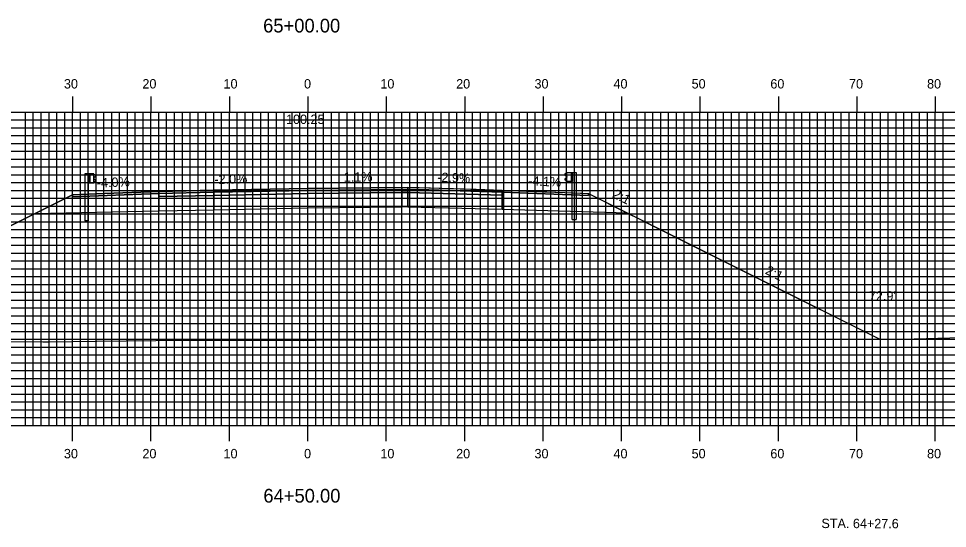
# Model space of a CAD drawing. Extents: x 1758643 to 1758986, y 442591 to 442811.
# Drawn here: x 1758771.8 to 1758890.2, y 442655.5 to 442720.6 of the extents above; entities that cross this region are included whole.
import ezdxf

# ---------------------------------------------------------------- set-up
doc = ezdxf.new("R2010")
doc.units = 0
for name, color, linetype in [('ANNOTATION', 7, 'Continuous'), ('BORING - REFUSAL', 7, 'Continuous'), ('D_Guardrail_Beam_Lt', 7, 'Continuous'), ('D_Guardrail_Beam_Rt', 7, 'Continuous'), ('D_Roadway_Centerline', 7, 'Continuous'), ('D_Roadway_Centerline_Text', 7, 'Continuous'), ('D_Roadway_Edge_Shoulder', 7, 'Continuous'), ('D_Roadway_Edge_TW', 7, 'Continuous'), ('D_Roadway_Pavement', 7, 'Continuous'), ('D_Roadway_SlopeLines', 7, 'Continuous'), ('D_Roadway_SubGrade', 7, 'Continuous'), ('D_Text_Standard', 7, 'Continuous'), ('H_V ANNOTATION', 7, 'Continuous'), ('MAJOR', 7, 'Continuous'), ('MINOR', 7, 'Continuous'), ('S_Roadway_Centerline', 7, 'Continuous')]:
    doc.layers.add(name, color=color, linetype=linetype)

msp = doc.modelspace()

# ---------------------------------------------------------------- linework, layer by layer
at = {"layer": 'D_Guardrail_Beam_Lt'}
for p, q in [((1758780.21, 442700.8), (1758780.21, 442694.8)), ((1758780.68, 442700.8), (1758780.21, 442700.8)), ((1758781.37, 442700.8), (1758780.68, 442700.8)), ((1758780.68, 442700.8), (1758780.68, 442699.63)), ((1758780.74, 442700.8), (1758780.74, 442699.63)), ((1758780.85, 442700.8), (1758780.85, 442699.63)), ((1758781.37, 442699.63), (1758781.37, 442700.8)), ((1758781.37, 442700.72), (1758781.44, 442700.7)), ((1758781.37, 442700.25), (1758781.37, 442700.18)), ((1758781.6, 442700.45), (1758781.41, 442700.31)), ((1758781.41, 442700.12), (1758781.6, 442699.98)), ((1758781.46, 442700.69), (1758781.6, 442700.59)), ((1758780.68, 442699.63), (1758781.37, 442699.63)), ((1758780.7, 442694.8), (1758780.7, 442699.63)), ((1758781.44, 442699.73), (1758781.37, 442699.72)), ((1758781.6, 442699.84), (1758781.46, 442699.74)), ((1758780.7, 442694.8), (1758780.21, 442694.8))]:
    msp.add_line(p, q, dxfattribs=at)
for centre, major_axis, start_param, end_param in [((1758781.45, 442700.25), (-0.0789, 0), 5.323254, 6.283185), ((1758781.45, 442700.18), (-0.0789, 0), 6.283185, 7.243116), ((1758781.43, 442700.66), (0.0417, 0), 0.959931, 1.376053), ((1758781.55, 442700.52), (0.0877, 0), 5.323254, 7.243116), ((1758781.43, 442699.77), (0.0417, 0), 4.907132, 5.323254), ((1758781.55, 442699.91), (0.0877, 0), 5.323254, 7.243116)]:
    msp.add_ellipse(centre, major_axis=major_axis, ratio=0.995501, start_param=start_param, end_param=end_param, dxfattribs=at)
at = {"layer": 'D_Guardrail_Beam_Rt'}
for p, q in [((1758841.6, 442700.87), (1758841.46, 442700.77)), ((1758841.46, 442700.62), (1758841.65, 442700.49)), ((1758841.65, 442700.29), (1758841.46, 442700.15)), ((1758841.69, 442700.89), (1758841.62, 442700.87)), ((1758841.69, 442700.97), (1758842.38, 442700.97)), ((1758841.69, 442699.81), (1758841.69, 442700.97)), ((1758841.69, 442700.42), (1758841.69, 442700.35)), ((1758842.21, 442700.97), (1758842.21, 442699.81)), ((1758842.32, 442700.97), (1758842.32, 442699.81)), ((1758842.38, 442700.97), (1758842.85, 442700.97)), ((1758842.38, 442700.97), (1758842.38, 442699.81)), ((1758842.85, 442700.97), (1758842.85, 442694.97)), ((1758841.46, 442700.01), (1758841.6, 442699.91)), ((1758841.62, 442699.9), (1758841.69, 442699.89)), ((1758842.38, 442699.81), (1758841.69, 442699.81)), ((1758842.36, 442694.97), (1758842.36, 442699.81)), ((1758842.36, 442694.97), (1758842.85, 442694.97))]:
    msp.add_line(p, q, dxfattribs=at)
for centre, major_axis, start_param, end_param in [((1758841.51, 442700.7), (-0.0877, 0), 5.323254, 7.243116), ((1758841.51, 442700.08), (-0.0877, 0), 5.323254, 7.243116), ((1758841.62, 442700.83), (-0.0417, 0), 4.907132, 5.323254), ((1758841.61, 442700.42), (0.0789, 0), 0, 0.959931), ((1758841.61, 442700.35), (0.0789, 0), 5.323254, 6.283185), ((1758841.62, 442699.94), (-0.0417, 0), 0.959931, 1.376053)]:
    msp.add_ellipse(centre, major_axis=major_axis, ratio=0.995501, start_param=start_param, end_param=end_param, dxfattribs=at)
at = {"layer": 'D_Roadway_Centerline'}
msp.add_lwpolyline([(1758740.03, 442678.79), (1758773.89, 442695.72), (1758778.64, 442698.1), (1758781.64, 442698.22), (1758789.64, 442698.54), (1758796.65, 442698.68), (1758808.65, 442698.92), (1758820.65, 442699.05), (1758821.41, 442699.06), (1758830.1, 442698.81), (1758833.42, 442698.71), (1758837.57, 442698.54), (1758841.42, 442698.39), (1758843.56, 442698.3), (1758844.42, 442698.27), (1758845.53, 442697.71), (1758849.39, 442695.78), (1758850.9, 442695.02), (1758852.29, 442694.33), (1758866.5, 442687.22), (1758881.57, 442679.68)], dxfattribs=at)
at = {"layer": 'D_Roadway_Edge_Shoulder'}
for points in [[(1758789.64, 442698.54), (1758781.64, 442698.22), (1758781.64, 442698.22), (1758778.64, 442698.1), (1758778.64, 442697.85), (1758789.64, 442698.29)], [(1758833.42, 442698.71), (1758841.42, 442698.39), (1758841.42, 442698.39), (1758844.42, 442698.27), (1758844.42, 442698.02), (1758833.42, 442698.46)]]:
    msp.add_lwpolyline(points, close=True, dxfattribs=at)
at = {"layer": 'D_Roadway_Edge_TW'}
for points in [[(1758820.65, 442698.8), (1758820.65, 442699.05), (1758808.65, 442698.92), (1758796.65, 442698.68), (1758796.65, 442698.43), (1758808.65, 442698.67)], [(1758820.65, 442699.05), (1758821.41, 442699.06), (1758821.41, 442698.81), (1758820.65, 442698.8)], [(1758821.41, 442699.06), (1758833.42, 442698.71), (1758833.42, 442698.46), (1758821.41, 442698.81)], [(1758796.65, 442698.68), (1758789.64, 442698.54), (1758789.64, 442698.29), (1758796.65, 442698.43)]]:
    msp.add_lwpolyline(points, close=True, dxfattribs=at)
msp.add_lwpolyline([(1758820.65, 442699.05), (1758820.65, 442698.8)], dxfattribs=at)
msp.add_lwpolyline([(1758820.65, 442699.05), (1758820.65, 442698.8)], dxfattribs=at)
at = {"layer": 'D_Roadway_Pavement'}
for points in [[(1758796.65, 442698.43), (1758789.64, 442698.29), (1758789.64, 442697.87), (1758796.65, 442698.01)], [(1758820.65, 442698.38), (1758820.65, 442698.8), (1758808.65, 442698.67), (1758796.65, 442698.43), (1758796.65, 442698.01), (1758808.65, 442698.25)], [(1758820.65, 442698.8), (1758821.41, 442698.81), (1758821.41, 442698.39), (1758820.65, 442698.38)], [(1758821.41, 442698.81), (1758833.42, 442698.46), (1758833.42, 442698.05), (1758821.41, 442698.39)]]:
    msp.add_lwpolyline(points, close=True, dxfattribs=at)
for points in [[(1758789.64, 442698.29), (1758789.64, 442697.87)], [(1758789.64, 442698.29), (1758789.64, 442697.87)], [(1758820.65, 442698.8), (1758820.65, 442698.38)], [(1758820.65, 442698.8), (1758820.65, 442698.38)], [(1758833.42, 442698.46), (1758833.42, 442698.05)], [(1758833.42, 442698.46), (1758833.42, 442698.05)]]:
    msp.add_lwpolyline(points, dxfattribs=at)
at = {"layer": 'D_Roadway_SlopeLines'}
for points in [[(1758778.64, 442698.1), (1758740.03, 442678.79)], [(1758844.42, 442698.27), (1758881.57, 442679.68)]]:
    msp.add_lwpolyline(points, dxfattribs=at)
at = {"layer": 'D_Roadway_SubGrade'}
for points in [[(1758789.64, 442697.87), (1758789.64, 442698.29), (1758778.64, 442697.85), (1758778.64, 442698.1), (1758773.89, 442695.72), (1758789.64, 442696.04)], [(1758796.65, 442698.01), (1758789.64, 442697.87), (1758789.64, 442696.04), (1758796.65, 442696.18)], [(1758820.65, 442696.55), (1758820.65, 442698.38), (1758808.65, 442698.25), (1758796.65, 442698.01), (1758796.65, 442696.18), (1758808.65, 442696.42)], [(1758820.65, 442698.38), (1758821.41, 442698.39), (1758821.41, 442696.53), (1758820.65, 442696.55)], [(1758821.41, 442698.39), (1758833.42, 442698.05), (1758833.42, 442696.21), (1758821.41, 442696.53)], [(1758833.42, 442698.05), (1758833.42, 442698.46), (1758844.42, 442698.02), (1758844.42, 442698.27), (1758849.39, 442695.78), (1758833.42, 442696.21)]]:
    msp.add_lwpolyline(points, close=True, dxfattribs=at)
msp.add_lwpolyline([(1758820.65, 442698.38), (1758820.65, 442696.55)], dxfattribs=at)
msp.add_lwpolyline([(1758820.65, 442698.38), (1758820.65, 442696.55)], dxfattribs=at)
at = {"layer": 'MAJOR'}
for p, q in [((1758778.65, 442710.67), (1758778.65, 442708.67)), ((1758788.65, 442710.67), (1758788.65, 442708.67)), ((1758798.65, 442710.67), (1758798.65, 442708.67)), ((1758808.65, 442710.67), (1758808.65, 442708.67)), ((1758818.65, 442710.67), (1758818.65, 442708.67)), ((1758828.65, 442710.67), (1758828.65, 442708.67)), ((1758838.65, 442710.67), (1758838.65, 442708.67)), ((1758848.65, 442710.67), (1758848.65, 442708.67)), ((1758858.65, 442710.67), (1758858.65, 442708.67)), ((1758868.65, 442710.67), (1758868.65, 442708.67)), ((1758878.65, 442710.67), (1758878.65, 442708.67)), ((1758888.65, 442710.67), (1758888.65, 442708.67)), ((1758668.65, 442708.67), (1758948.65, 442708.67)), ((1758668.65, 442708.67), (1758948.65, 442708.67)), ((1758778.65, 442668.67), (1758778.65, 442708.67)), ((1758788.65, 442668.67), (1758788.65, 442708.67)), ((1758798.65, 442668.67), (1758798.65, 442708.67)), ((1758808.65, 442668.67), (1758808.65, 442708.67)), ((1758818.65, 442668.67), (1758818.65, 442708.67)), ((1758828.65, 442668.67), (1758828.65, 442708.67)), ((1758838.65, 442668.67), (1758838.65, 442708.67)), ((1758848.65, 442668.67), (1758848.65, 442708.67)), ((1758858.65, 442668.67), (1758858.65, 442708.67)), ((1758868.65, 442668.67), (1758868.65, 442708.67)), ((1758878.65, 442668.67), (1758878.65, 442708.67)), ((1758888.65, 442668.67), (1758888.65, 442708.67)), ((1758668.65, 442703.67), (1758948.65, 442703.67)), ((1758668.65, 442698.67), (1758948.65, 442698.67)), ((1758668.65, 442693.67), (1758948.65, 442693.67)), ((1758668.65, 442688.67), (1758948.65, 442688.67)), ((1758668.65, 442683.67), (1758948.65, 442683.67)), ((1758668.65, 442678.67), (1758948.65, 442678.67)), ((1758668.65, 442673.67), (1758948.65, 442673.67)), ((1758668.65, 442668.67), (1758948.65, 442668.67)), ((1758668.65, 442668.67), (1758948.65, 442668.67)), ((1758778.65, 442666.66), (1758778.65, 442668.67)), ((1758788.65, 442666.66), (1758788.65, 442668.67)), ((1758798.65, 442666.66), (1758798.65, 442668.67)), ((1758808.65, 442666.66), (1758808.65, 442668.67)), ((1758818.65, 442666.66), (1758818.65, 442668.67)), ((1758828.65, 442666.66), (1758828.65, 442668.67)), ((1758838.65, 442666.66), (1758838.65, 442668.67)), ((1758848.65, 442666.66), (1758848.65, 442668.67)), ((1758858.65, 442666.66), (1758858.65, 442668.67)), ((1758868.65, 442666.66), (1758868.65, 442668.67)), ((1758878.65, 442666.66), (1758878.65, 442668.67)), ((1758888.65, 442666.66), (1758888.65, 442668.67))]:
    msp.add_line(p, q, dxfattribs=at)
at = {"layer": 'MINOR'}
for p, q in [((1758772.65, 442668.67), (1758772.65, 442708.67)), ((1758773.65, 442668.67), (1758773.65, 442708.67)), ((1758774.65, 442668.67), (1758774.65, 442708.67)), ((1758775.65, 442668.67), (1758775.65, 442708.67)), ((1758776.65, 442668.67), (1758776.65, 442708.67)), ((1758777.65, 442668.67), (1758777.65, 442708.67)), ((1758779.65, 442668.67), (1758779.65, 442708.67)), ((1758780.65, 442668.67), (1758780.65, 442708.67)), ((1758781.65, 442668.67), (1758781.65, 442708.67)), ((1758782.65, 442668.67), (1758782.65, 442708.67)), ((1758783.65, 442668.67), (1758783.65, 442708.67)), ((1758784.65, 442668.67), (1758784.65, 442708.67)), ((1758785.65, 442668.67), (1758785.65, 442708.67)), ((1758786.65, 442668.67), (1758786.65, 442708.67)), ((1758787.65, 442668.67), (1758787.65, 442708.67)), ((1758789.65, 442668.67), (1758789.65, 442708.67)), ((1758790.65, 442668.67), (1758790.65, 442708.67)), ((1758791.65, 442668.67), (1758791.65, 442708.67)), ((1758792.65, 442668.67), (1758792.65, 442708.67)), ((1758793.65, 442668.67), (1758793.65, 442708.67)), ((1758794.65, 442668.67), (1758794.65, 442708.67)), ((1758795.65, 442668.67), (1758795.65, 442708.67)), ((1758796.65, 442668.67), (1758796.65, 442708.67)), ((1758797.65, 442668.67), (1758797.65, 442708.67)), ((1758799.65, 442668.67), (1758799.65, 442708.67)), ((1758800.65, 442668.67), (1758800.65, 442708.67)), ((1758801.65, 442668.67), (1758801.65, 442708.67)), ((1758802.65, 442668.67), (1758802.65, 442708.67)), ((1758803.65, 442668.67), (1758803.65, 442708.67)), ((1758804.65, 442668.67), (1758804.65, 442708.67)), ((1758805.65, 442668.67), (1758805.65, 442708.67)), ((1758806.65, 442668.67), (1758806.65, 442708.67)), ((1758807.65, 442668.67), (1758807.65, 442708.67)), ((1758809.65, 442668.67), (1758809.65, 442708.67)), ((1758810.65, 442668.67), (1758810.65, 442708.67)), ((1758811.65, 442668.67), (1758811.65, 442708.67)), ((1758812.65, 442668.67), (1758812.65, 442708.67)), ((1758813.65, 442668.67), (1758813.65, 442708.67)), ((1758814.65, 442668.67), (1758814.65, 442708.67)), ((1758815.65, 442668.67), (1758815.65, 442708.67)), ((1758816.65, 442668.67), (1758816.65, 442708.67)), ((1758817.65, 442668.67), (1758817.65, 442708.67)), ((1758819.65, 442668.67), (1758819.65, 442708.67)), ((1758820.65, 442668.67), (1758820.65, 442708.67)), ((1758821.65, 442668.67), (1758821.65, 442708.67)), ((1758822.65, 442668.67), (1758822.65, 442708.67)), ((1758823.65, 442668.67), (1758823.65, 442708.67)), ((1758824.65, 442668.67), (1758824.65, 442708.67)), ((1758825.65, 442668.67), (1758825.65, 442708.67)), ((1758826.65, 442668.67), (1758826.65, 442708.67)), ((1758827.65, 442668.67), (1758827.65, 442708.67)), ((1758829.65, 442668.67), (1758829.65, 442708.67)), ((1758830.65, 442668.67), (1758830.65, 442708.67)), ((1758831.65, 442668.67), (1758831.65, 442708.67)), ((1758832.65, 442668.67), (1758832.65, 442708.67)), ((1758833.65, 442668.67), (1758833.65, 442708.67)), ((1758834.65, 442668.67), (1758834.65, 442708.67)), ((1758835.65, 442668.67), (1758835.65, 442708.67)), ((1758836.65, 442668.67), (1758836.65, 442708.67)), ((1758837.65, 442668.67), (1758837.65, 442708.67)), ((1758839.65, 442668.67), (1758839.65, 442708.67)), ((1758840.65, 442668.67), (1758840.65, 442708.67)), ((1758841.65, 442668.67), (1758841.65, 442708.67)), ((1758842.65, 442668.67), (1758842.65, 442708.67)), ((1758843.65, 442668.67), (1758843.65, 442708.67)), ((1758844.65, 442668.67), (1758844.65, 442708.67)), ((1758845.65, 442668.67), (1758845.65, 442708.67)), ((1758846.65, 442668.67), (1758846.65, 442708.67)), ((1758847.65, 442668.67), (1758847.65, 442708.67)), ((1758849.65, 442668.67), (1758849.65, 442708.67)), ((1758850.65, 442668.67), (1758850.65, 442708.67)), ((1758851.65, 442668.67), (1758851.65, 442708.67)), ((1758852.65, 442668.67), (1758852.65, 442708.67)), ((1758853.65, 442668.67), (1758853.65, 442708.67)), ((1758854.65, 442668.67), (1758854.65, 442708.67)), ((1758855.65, 442668.67), (1758855.65, 442708.67)), ((1758856.65, 442668.67), (1758856.65, 442708.67)), ((1758857.65, 442668.67), (1758857.65, 442708.67)), ((1758859.65, 442668.67), (1758859.65, 442708.67)), ((1758860.65, 442668.67), (1758860.65, 442708.67)), ((1758861.65, 442668.67), (1758861.65, 442708.67)), ((1758862.65, 442668.67), (1758862.65, 442708.67)), ((1758863.65, 442668.67), (1758863.65, 442708.67)), ((1758864.65, 442668.67), (1758864.65, 442708.67)), ((1758865.65, 442668.67), (1758865.65, 442708.67)), ((1758866.65, 442668.67), (1758866.65, 442708.67)), ((1758867.65, 442668.67), (1758867.65, 442708.67)), ((1758869.65, 442668.67), (1758869.65, 442708.67)), ((1758870.65, 442668.67), (1758870.65, 442708.67)), ((1758871.65, 442668.67), (1758871.65, 442708.67)), ((1758872.65, 442668.67), (1758872.65, 442708.67)), ((1758873.65, 442668.67), (1758873.65, 442708.67)), ((1758874.65, 442668.67), (1758874.65, 442708.67)), ((1758875.65, 442668.67), (1758875.65, 442708.67)), ((1758876.65, 442668.67), (1758876.65, 442708.67)), ((1758877.65, 442668.67), (1758877.65, 442708.67)), ((1758879.65, 442668.67), (1758879.65, 442708.67)), ((1758880.65, 442668.67), (1758880.65, 442708.67)), ((1758881.65, 442668.67), (1758881.65, 442708.67)), ((1758882.65, 442668.67), (1758882.65, 442708.67)), ((1758883.65, 442668.67), (1758883.65, 442708.67)), ((1758884.65, 442668.67), (1758884.65, 442708.67)), ((1758885.65, 442668.67), (1758885.65, 442708.67)), ((1758886.65, 442668.67), (1758886.65, 442708.67)), ((1758887.65, 442668.67), (1758887.65, 442708.67)), ((1758889.65, 442668.67), (1758889.65, 442708.67)), ((1758668.65, 442707.67), (1758948.65, 442707.67)), ((1758668.65, 442706.67), (1758948.65, 442706.67)), ((1758668.65, 442705.67), (1758948.65, 442705.67)), ((1758668.65, 442704.67), (1758948.65, 442704.67)), ((1758668.65, 442702.67), (1758948.65, 442702.67)), ((1758668.65, 442701.67), (1758948.65, 442701.67)), ((1758668.65, 442700.67), (1758948.65, 442700.67)), ((1758668.65, 442699.67), (1758948.65, 442699.67)), ((1758668.65, 442697.67), (1758948.65, 442697.67)), ((1758668.65, 442696.67), (1758948.65, 442696.67)), ((1758668.65, 442695.67), (1758948.65, 442695.67)), ((1758668.65, 442694.67), (1758948.65, 442694.67)), ((1758668.65, 442692.67), (1758948.65, 442692.67)), ((1758668.65, 442691.67), (1758948.65, 442691.67)), ((1758668.65, 442690.67), (1758948.65, 442690.67)), ((1758668.65, 442689.67), (1758948.65, 442689.67)), ((1758668.65, 442687.67), (1758948.65, 442687.67)), ((1758668.65, 442686.67), (1758948.65, 442686.67)), ((1758668.65, 442685.67), (1758948.65, 442685.67)), ((1758668.65, 442684.67), (1758948.65, 442684.67)), ((1758668.65, 442682.67), (1758948.65, 442682.67)), ((1758668.65, 442681.67), (1758948.65, 442681.67)), ((1758668.65, 442680.67), (1758948.65, 442680.67)), ((1758668.65, 442679.67), (1758948.65, 442679.67)), ((1758668.65, 442677.67), (1758948.65, 442677.67)), ((1758668.65, 442676.67), (1758948.65, 442676.67)), ((1758668.65, 442675.67), (1758948.65, 442675.67)), ((1758668.65, 442674.67), (1758948.65, 442674.67)), ((1758668.65, 442672.67), (1758948.65, 442672.67)), ((1758668.65, 442671.67), (1758948.65, 442671.67)), ((1758668.65, 442670.67), (1758948.65, 442670.67)), ((1758668.65, 442669.67), (1758948.65, 442669.67))]:
    msp.add_line(p, q, dxfattribs=at)
at = {"layer": 'S_Roadway_Centerline'}
msp.add_lwpolyline([(1758758, 442679.38), (1758774.87, 442679.33), (1758775.55, 442679.35), (1758781.75, 442679.42), (1758793.01, 442679.55), (1758794.13, 442679.56), (1758808.13, 442679.52), (1758808.73, 442679.54), (1758809.61, 442679.54), (1758825.77, 442679.62), (1758839.23, 442679.51), (1758845.34, 442679.57), (1758859.56, 442679.76), (1758866.11, 442679.7), (1758884.61, 442679.67), (1758885.94, 442679.72), (1758899.57, 442680.1)], dxfattribs=at)

# ---------------------------------------------------------------- texts
at = {"layer": 'ANNOTATION'}
for s, rotation, p in [('-4.0%', 2.2906, (1758781.77, 442699.02)), ('-2.0%', 1.1458, (1758796.75, 442699.48)), ('1.1%', 0.6426, (1758813.24, 442699.77)), ('-2.9%', 358.3563, (1758825.14, 442699.75)), ('-4.1%', 357.6747, (1758836.73, 442699.3)), ('2:1', 333.4175, (1758847.39, 442697.82)), ('2:1', 333.4173, (1758866.87, 442688.07))]:
    msp.add_text(s, height=1.2, rotation=rotation, dxfattribs=at).set_placement(p)
at = {"layer": 'BORING - REFUSAL'}
msp.add_text('STA. 64+27.6', height=1.2, rotation=359.8142, dxfattribs=at).set_placement((1758874.13, 442655.57))
at = {"layer": 'D_Roadway_Centerline'}
for s, p in [('C', (1758808.64, 442698.92)), ('L', (1758808.65, 442698.91))]:
    msp.add_text(s, height=0.0146, dxfattribs=at).set_placement(p)
at = {"layer": 'D_Roadway_Centerline_Text'}
msp.add_text('100.25', height=1.2, dxfattribs=at).set_placement((1758805.87, 442707.14))
at = {"layer": 'D_Text_Standard'}
msp.add_text("72.9'", height=1.2, dxfattribs=at).set_placement((1758880.19, 442684.6))
at = {"layer": 'H_V ANNOTATION'}
for s, height, p in [('65+00.00', 1.75, (1758802.95, 442718.82)), ('30', 1.2, (1758777.55, 442711.67)), ('20', 1.2, (1758787.56, 442711.67)), ('10', 1.2, (1758797.9, 442711.67)), ('0', 1.2, (1758808.17, 442711.67)), ('10', 1.2, (1758817.9, 442711.67)), ('20', 1.2, (1758827.56, 442711.67)), ('30', 1.2, (1758837.55, 442711.67)), ('40', 1.2, (1758847.62, 442711.67)), ('50', 1.2, (1758857.58, 442711.67)), ('60', 1.2, (1758867.62, 442711.67)), ('70', 1.2, (1758877.65, 442711.67)), ('80', 1.2, (1758887.6, 442711.67)), ('30', 1.2, (1758777.55, 442664.47)), ('20', 1.2, (1758787.56, 442664.47)), ('10', 1.2, (1758797.9, 442664.47)), ('0', 1.2, (1758808.17, 442664.47)), ('10', 1.2, (1758817.9, 442664.47)), ('20', 1.2, (1758827.56, 442664.47)), ('30', 1.2, (1758837.55, 442664.47)), ('40', 1.2, (1758847.62, 442664.47)), ('50', 1.2, (1758857.58, 442664.47)), ('60', 1.2, (1758867.62, 442664.47)), ('70', 1.2, (1758877.65, 442664.47)), ('80', 1.2, (1758887.6, 442664.47)), ('64+50.00', 1.75, (1758802.98, 442658.82))]:
    msp.add_text(s, height=height, dxfattribs=at).set_placement(p)

doc.saveas('drawing.dxf')
